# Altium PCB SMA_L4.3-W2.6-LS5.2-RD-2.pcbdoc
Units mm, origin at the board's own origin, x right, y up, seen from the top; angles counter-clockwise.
Board outline 18.96 x 15.7 mm, 2 copper layers (Top Layer, Bottom Layer), stack 0 mm thick; 1 components, 0 nets, 2 pads, 0 vias.
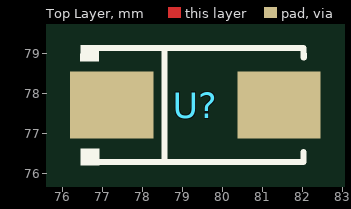
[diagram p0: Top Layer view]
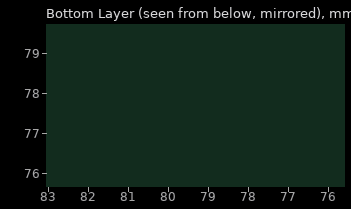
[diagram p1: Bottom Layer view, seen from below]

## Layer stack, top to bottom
Top Layer: signal copper (thickness not stored)
Bottom Layer: signal copper (thickness not stored)

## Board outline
88.81,69.85 69.85,69.85 69.85,85.555 88.81,85.555

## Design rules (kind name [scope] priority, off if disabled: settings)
PasteMaskExpansion "Paste Mask Expansion" [All] p1: expansion=0
SolderMaskExpansion "Solder Mask Expansion" [IsVia] p1: expansion=-25.4 istentingtop=TRUE
SolderMaskExpansion "Solder Mask Expansion" [All] p2: expansion=0.051 istentingtop=FALSE

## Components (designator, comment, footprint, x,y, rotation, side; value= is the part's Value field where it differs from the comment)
U? "" SMA_L4.3-W2.6-LS5.2-RD-2 79.33,77.703 r0 top

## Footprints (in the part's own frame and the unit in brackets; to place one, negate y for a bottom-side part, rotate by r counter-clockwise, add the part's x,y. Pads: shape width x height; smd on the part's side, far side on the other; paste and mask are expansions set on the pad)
SMA_L4.3-W2.6-LS5.2-RD-2 [mm]
  rect 2.08x1.67 smd: 1(-2.09,0) 2(2.09,0)
  silkscreen extent -2.87,-1.5 2.71,1.5

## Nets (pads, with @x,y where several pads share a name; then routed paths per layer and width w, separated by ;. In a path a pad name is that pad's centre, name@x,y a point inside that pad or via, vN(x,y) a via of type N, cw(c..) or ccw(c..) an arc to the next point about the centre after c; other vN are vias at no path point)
pads on no net: U?.1 U?.2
